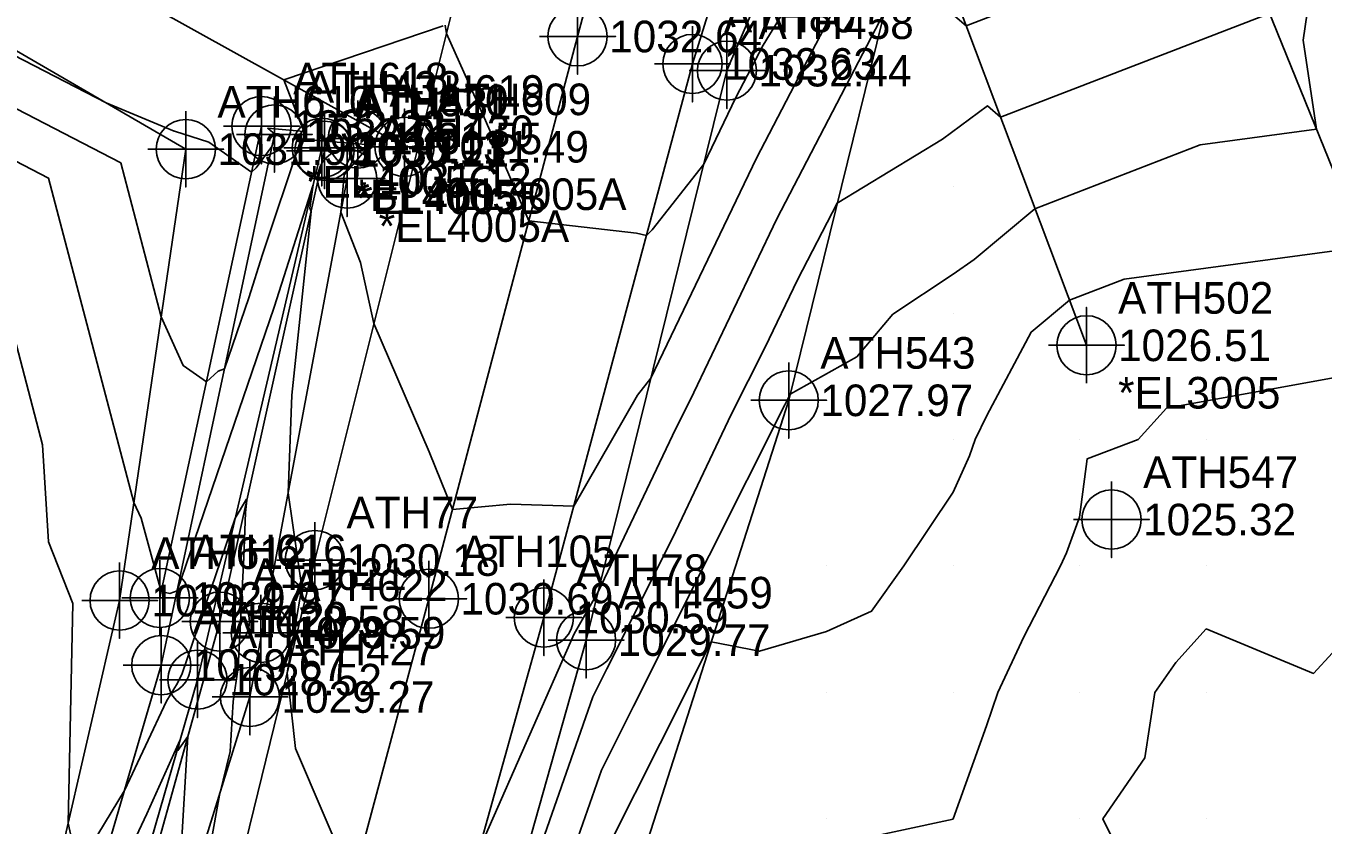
# Model space of a CAD drawing. Extents: x 1213164 to 1213550, y 766120 to 766870.
# Drawn here: x 1213316.7 to 1213419.3, y 766539.5 to 766602.7 of the extents above; entities that cross this region are included whole.
import ezdxf

# ---------------------------------------------------------------- set-up
doc = ezdxf.new("R2010")
doc.units = 0
for name, color, linetype in [('Default', 7, 'Continuous'), ('Exist DTM Breakline', 7, 'Continuous'), ('Exist DTM Breakline Cogo Comment', 7, 'Continuous'), ('Exist DTM Breakline Cogo Elevation', 7, 'Continuous'), ('Exist DTM Breakline Cogo Number', 7, 'Continuous'), ('Exist DTM Breakline Cogo Point CELL', 7, 'Continuous'), ('Exist DTM Crownline', 7, 'Continuous'), ('Exist DTM Crownline Cogo Elevation', 7, 'Continuous'), ('Exist DTM Crownline Cogo Number', 7, 'Continuous'), ('Exist DTM Crownline Cogo Point CELL', 7, 'Continuous'), ('Exist DTM QL2 LIDAR Elevation Point', 7, 'Continuous'), ('Exist DTM Regular Point CELL', 7, 'Continuous'), ('Exist DTM Regular Point Cogo Elevation', 7, 'Continuous'), ('Exist DTM Regular Point Cogo Number', 7, 'Continuous'), ('Exist Roads EOP', 7, 'Continuous'), ('Exist Roads EOP Cogo Elevation', 7, 'Continuous'), ('Exist Roads EOP Cogo Number', 7, 'Continuous'), ('Exist Roads EOP Cogo Point CELL', 7, 'Continuous'), ('Exist Roads Soil', 7, 'Continuous'), ('Exist Roads Soil Cogo Comment', 7, 'Continuous'), ('Exist Roads Soil Cogo Elevation', 7, 'Continuous'), ('Exist Roads Soil Cogo Number', 7, 'Continuous'), ('Exist Roads Soil Cogo Point CELL', 7, 'Continuous')]:
    doc.layers.add(name, color=color, linetype=linetype)

msp = doc.modelspace()

# ---------------------------------------------------------------- linework, layer by layer
at = {"layer": 'Default'}
for points in [[(1213353.03, 766538.71), (1213360.06, 766554.63), (1213361.94, 766557.96), (1213368.09, 766570.88), (1213369.21, 766573.11), (1213376.08, 766587.44), (1213384.56, 766603.77), (1213386.66, 766605.05), (1213387.56, 766605.71), (1213391.04, 766602.72), (1213405.84, 766608.43), (1213411.21, 766613.12), (1213411.8, 766620.77), (1213412.59, 766627.41), (1213412.01, 766629.52), (1213413.41, 766632.98), (1213419.7, 766639.25), (1213420, 766639.17), (1213420.37, 766639.63), (1213420.63, 766640), (1213424.33, 766645.67), (1213426.37, 766650), (1213427.85, 766652.15), (1213430, 766656.29)], [(1213353.14, 766525.66), (1213361.52, 766549.65), (1213362.63, 766551.86), (1213367.85, 766562.26), (1213372.47, 766571.97), (1213375.15, 766577.31), (1213377.7, 766582.63), (1213380.85, 766588.68), (1213389.17, 766593.76), (1213392.72, 766596.38), (1213393.76, 766595.49), (1213414.67, 766603.56), (1213414.97, 766603.82), (1213415.01, 766604.26), (1213417.21, 766622.79), (1213415.71, 766628.28), (1213420, 766627.19)], [(1213356.49, 766527.5), (1213362.2, 766543.86), (1213364.74, 766548.91), (1213376.71, 766572.75), (1213376.86, 766573.06), (1213377.13, 766573.6), (1213382.4, 766576.55), (1213385.24, 766579.91), (1213390, 766583.08), (1213391.68, 766584.23), (1213396.48, 766588.25), (1213409.54, 766593.3), (1213418.74, 766594.53), (1213417.67, 766601.59), (1213418.64, 766608.1), (1213420, 766614.82)], [(1213304.7, 766601.97), (1213324.2, 766591.88), (1213327.4, 766579.7), (1213329.15, 766575.85), (1213330.98, 766574.56), (1213331.9, 766575.41), (1213332.4, 766575.6), (1213334.32, 766581.21), (1213335.41, 766584.62), (1213338.39, 766593.55), (1213338.09, 766593.79), (1213343.9, 766593.31), (1213343.81, 766593.21), (1213341.87, 766590.92), (1213341.6, 766587.97), (1213343.17, 766584), (1213344.22, 766579.18), (1213348.58, 766569.03), (1213350.43, 766564.48), (1213355.02, 766564.88), (1213360.02, 766564.74), (1213365.05, 766573.5), (1213366.12, 766574.86), (1213374.46, 766592.25), (1213381.5, 766605.8)], [(1213305.99, 766605.45), (1213323.05, 766596.62), (1213328.43, 766594.38), (1213328.45, 766594.38), (1213331.18, 766593.52), (1213334.55, 766591.15), (1213334.92, 766591.49), (1213336.14, 766593.18), (1213336.45, 766594.1), (1213335.83, 766594.61), (1213338.68, 766594.37), (1213337.1, 766598.45), (1213349.69, 766602.72)], [(1213349.86, 766602.78), (1213349.95, 766602.12), (1213353.05, 766595.24), (1213356.46, 766587.3), (1213364.99, 766586.31), (1213365.76, 766586.13), (1213366.22, 766586.57), (1213370.3, 766591.77), (1213372.84, 766597.06), (1213374.99, 766601.19), (1213376.71, 766603.99)], [(1213303.41, 766598.49), (1213318.49, 766590.68), (1213325.25, 766565.01), (1213325.81, 766563.78), (1213327.41, 766557.97), (1213328.09, 766557.82), (1213328.66, 766558.03), (1213336.34, 766580.47), (1213339.42, 766590.13), (1213339.16, 766588.3), (1213339.25, 766588.02), (1213337.74, 766573.52), (1213337.45, 766565.79), (1213338.52, 766558.29), (1213337.37, 766551.56), (1213338.03, 766545.56), (1213342.55, 766534.96)], [(1213312.79, 766589.49), (1213318.03, 766569.59), (1213318.49, 766561.9), (1213320.42, 766557.04), (1213320.05, 766539.66), (1213320.82, 766536.16), (1213324.49, 766542.24), (1213327.82, 766549.3), (1213328.69, 766550.73), (1213329.06, 766551.49), (1213333.25, 766563.77), (1213334.15, 766565.28), (1213334.18, 766565.2), (1213334.08, 766564.24), (1213333.94, 766560.68), (1213333.49, 766551.98), (1213333.09, 766549.29), (1213332.85, 766545.34), (1213332.01, 766541.89), (1213329.93, 766530.39)], [(1213362.88, 766538.06), (1213366.85, 766545.97), (1213370.89, 766554.01), (1213374.7, 766553.26), (1213380, 766554.82), (1213383.56, 766556.44), (1213386.12, 766560), (1213390, 766565.83), (1213391.29, 766568.71), (1213391.76, 766570), (1213392.68, 766571.89), (1213396.19, 766578.5), (1213399.2, 766581.02), (1213403.52, 766582.69), (1213422.5, 766585.23)], [(1213381.8, 766538.2), (1213390, 766539.99), (1213390, 766539.99), (1213390.01, 766540), (1213392.64, 766547.36), (1213393.53, 766550), (1213395.59, 766554.41), (1213398.5, 766560), (1213398.97, 766561.03), (1213400, 766563.85), (1213400.61, 766568.48), (1213404.63, 766570), (1213406.87, 766572.47), (1213424.68, 766575.72)], [(1213403.65, 766536.35), (1213401.85, 766540), (1213405.16, 766544.84), (1213405.95, 766550), (1213407.62, 766552.38), (1213410, 766555.03), (1213418.49, 766551.51), (1213420, 766553.14), (1213421.59, 766550), (1213421.87, 766548.13), (1213424.23, 766540), (1213426.51, 766533.49)], [(1213320.12, 766527.35), (1213326.28, 766540.39), (1213328.88, 766546.21), (1213328.73, 766545.41), (1213329.52, 766546.52), (1213328.95, 766537.12)]]:
    msp.add_lwpolyline(points, dxfattribs=at)
at = {"layer": 'Exist DTM Breakline'}
msp.add_line((1213335.33, 766594.79), (1213327.3, 766557.47), dxfattribs=at)
for points in [[(1213396.81, 766643.38), (1213385.25, 766629.79), (1213372.13, 766599.17), (1213360.99, 766554.14), (1213352.93, 766525.55), (1213348.45, 766509.5)], [(1213233.32, 766620.63), (1213306.32, 766606.35), (1213329.35, 766592.96), (1213324.12, 766557.27), (1213317.07, 766526.75)], [(1213385.82, 766608.86), (1213377.01, 766573.1), (1213363.67, 766531.44)], [(1213318.46, 766521.69), (1213327.41, 766552.16), (1213336.35, 766594.13)], [(1213340.32, 766592.83), (1213332.04, 766555.6), (1213323.54, 766524.98), (1213320.37, 766516.25)], [(1213321.01, 766518.9), (1213330.27, 766551.01), (1213340.1, 766593.06)], [(1213324.6, 766518.12), (1213334.42, 766549.64), (1213342.1, 766590.63)]]:
    msp.add_lwpolyline(points, dxfattribs=at)
at = {"layer": 'Exist DTM Breakline Cogo Point CELL'}
for points in [[(1213372.13, 766602.17), (1213372.13, 766596.17), (1213372.13, 766599.17), (1213375.13, 766599.17), (1213369.13, 766599.17)], [(1213335.33, 766597.79), (1213335.33, 766591.79), (1213335.33, 766594.79), (1213338.33, 766594.79), (1213332.33, 766594.79)], [(1213336.35, 766597.13), (1213336.35, 766591.13), (1213336.35, 766594.13), (1213339.35, 766594.13), (1213333.35, 766594.13)], [(1213329.35, 766595.96), (1213329.35, 766589.96), (1213329.35, 766592.96), (1213332.35, 766592.96), (1213326.35, 766592.96)], [(1213340.1, 766596.06), (1213340.1, 766590.06), (1213340.1, 766593.06), (1213343.1, 766593.06), (1213337.1, 766593.06)], [(1213342.94, 766596.81), (1213342.94, 766590.81), (1213342.94, 766593.81), (1213345.94, 766593.81), (1213339.94, 766593.81)], [(1213340.32, 766595.83), (1213340.32, 766589.83), (1213340.32, 766592.83), (1213343.32, 766592.83), (1213337.32, 766592.83)], [(1213342.1, 766593.63), (1213342.1, 766587.63), (1213342.1, 766590.63), (1213345.1, 766590.63), (1213339.1, 766590.63)], [(1213377.01, 766576.1), (1213377.01, 766570.1), (1213377.01, 766573.1), (1213380.01, 766573.1), (1213374.01, 766573.1)], [(1213324.12, 766560.27), (1213324.12, 766554.27), (1213324.12, 766557.27), (1213327.12, 766557.27), (1213321.12, 766557.27)], [(1213327.3, 766560.47), (1213327.3, 766554.47), (1213327.3, 766557.47), (1213330.3, 766557.47), (1213324.3, 766557.47)], [(1213332.04, 766558.6), (1213332.04, 766552.6), (1213332.04, 766555.6), (1213335.04, 766555.6), (1213329.04, 766555.6)], [(1213335.28, 766557.72), (1213335.28, 766551.72), (1213335.28, 766554.72), (1213338.28, 766554.72), (1213332.28, 766554.72)], [(1213360.99, 766557.14), (1213360.99, 766551.14), (1213360.99, 766554.14), (1213363.99, 766554.14), (1213357.99, 766554.14)], [(1213327.41, 766555.16), (1213327.41, 766549.16), (1213327.41, 766552.16), (1213330.41, 766552.16), (1213324.41, 766552.16)], [(1213330.27, 766554.01), (1213330.27, 766548.01), (1213330.27, 766551.01), (1213333.27, 766551.01), (1213327.27, 766551.01)], [(1213334.42, 766552.64), (1213334.42, 766546.64), (1213334.42, 766549.64), (1213337.42, 766549.64), (1213331.42, 766549.64)]]:
    msp.add_lwpolyline(points, dxfattribs=at)
for centre in [(1213372.13, 766599.17), (1213335.33, 766594.79), (1213336.35, 766594.13), (1213342.94, 766593.81), (1213329.35, 766592.96), (1213340.1, 766593.06), (1213340.32, 766592.83), (1213342.1, 766590.63), (1213377.01, 766573.1), (1213324.12, 766557.27), (1213327.3, 766557.47), (1213332.04, 766555.6), (1213335.28, 766554.72), (1213360.99, 766554.14), (1213327.41, 766552.16), (1213330.27, 766551.01), (1213334.42, 766549.64)]:
    msp.add_circle(centre, 2.34, dxfattribs=at)
at = {"layer": 'Exist DTM Crownline'}
msp.add_lwpolyline([(1213369.87, 766637.44), (1213360.32, 766601.88), (1213348.56, 766557.41), (1213336.15, 766511.05)], dxfattribs=at)
at = {"layer": 'Exist DTM Crownline Cogo Point CELL'}
for points in [[(1213360.32, 766604.88), (1213360.32, 766598.88), (1213360.32, 766601.88), (1213363.32, 766601.88), (1213357.32, 766601.88)], [(1213348.56, 766560.41), (1213348.56, 766554.41), (1213348.56, 766557.41), (1213351.56, 766557.41), (1213345.56, 766557.41)]]:
    msp.add_lwpolyline(points, dxfattribs=at)
for centre in [(1213360.32, 766601.88), (1213348.56, 766557.41)]:
    msp.add_circle(centre, 2.34, dxfattribs=at)
at = {"layer": 'Exist DTM QL2 LIDAR Elevation Point'}
for p, q in [((1213390, 766590), (1213390, 766590)), ((1213390, 766580), (1213390, 766580)), ((1213390, 766570), (1213390, 766570)), ((1213400, 766570), (1213400, 766570)), ((1213410, 766570), (1213410, 766570)), ((1213380, 766560), (1213380, 766560)), ((1213390, 766560), (1213390, 766560)), ((1213400, 766560), (1213400, 766560)), ((1213410, 766560), (1213410, 766560)), ((1213380, 766550), (1213380, 766550)), ((1213390, 766550), (1213390, 766550)), ((1213400, 766550), (1213400, 766550)), ((1213410, 766550), (1213410, 766550)), ((1213380, 766540), (1213380, 766540)), ((1213390, 766540), (1213390, 766540)), ((1213400, 766540), (1213400, 766540)), ((1213410, 766540), (1213410, 766540))]:
    msp.add_line(p, q, dxfattribs=at)
at = {"layer": 'Exist DTM Regular Point CELL'}
msp.add_lwpolyline([(1213402.53, 766566.67), (1213402.53, 766560.67), (1213402.53, 766563.67), (1213405.53, 766563.67), (1213399.53, 766563.67)], dxfattribs=at)
msp.add_circle((1213402.53, 766563.67), 2.34, dxfattribs=at)
at = {"layer": 'Exist Roads EOP'}
for points in [[(1213344.56, 766509.06), (1213357.66, 766555.92), (1213369.4, 766599.7), (1213380.5, 766635.51), (1213390.23, 766668.75)], [(1213327.95, 766513.13), (1213339.55, 766560.47), (1213350.85, 766605.72), (1213360.68, 766641.43)]]:
    msp.add_lwpolyline(points, dxfattribs=at)
at = {"layer": 'Exist Roads EOP Cogo Point CELL'}
for points in [[(1213369.4, 766602.7), (1213369.4, 766596.7), (1213369.4, 766599.7), (1213372.4, 766599.7), (1213366.4, 766599.7)], [(1213339.55, 766563.47), (1213339.55, 766557.47), (1213339.55, 766560.47), (1213342.55, 766560.47), (1213336.55, 766560.47)], [(1213357.66, 766558.92), (1213357.66, 766552.92), (1213357.66, 766555.92), (1213360.66, 766555.92), (1213354.66, 766555.92)]]:
    msp.add_lwpolyline(points, dxfattribs=at)
for centre in [(1213369.4, 766599.7), (1213339.55, 766560.47), (1213357.66, 766555.92)]:
    msp.add_circle(centre, 2.34, dxfattribs=at)
at = {"layer": 'Exist Roads Soil'}
msp.add_line((1213426.4, 766575.59), (1213398.12, 766645.45), dxfattribs=at)
for points in [[(1213233.88, 766629.04), (1213261.45, 766622.83), (1213319.9, 766608), (1213346.63, 766593.15)], [(1213384.45, 766620.24), (1213400.55, 766577.45)]]:
    msp.add_lwpolyline(points, dxfattribs=at)
at = {"layer": 'Exist Roads Soil Cogo Point CELL'}
for points in [[(1213346.63, 766590.15), (1213346.63, 766596.15), (1213346.63, 766593.15), (1213349.63, 766593.15), (1213343.63, 766593.15)], [(1213400.55, 766574.45), (1213400.55, 766580.45), (1213400.55, 766577.45), (1213403.55, 766577.45), (1213397.55, 766577.45)]]:
    msp.add_lwpolyline(points, dxfattribs=at)
for centre in [(1213346.63, 766593.15), (1213400.55, 766577.45)]:
    msp.add_circle(centre, 2.34, dxfattribs=at)

# ---------------------------------------------------------------- texts
at = {"layer": 'Exist DTM Breakline Cogo Comment'}
for s, p in [('*EL4005C', (1213338.85, 766589.13)), ('*BL4005', (1213342.6, 766588.06)), ('*EL4005B', (1213342.82, 766587.83)), ('*EL4005A', (1213344.6, 766585.63))]:
    msp.add_text(s, height=2.5, dxfattribs=at).set_placement(p)
at = {"layer": 'Exist DTM Breakline Cogo Elevation'}
for s, p in [('1032.44', (1213374.63, 766597.92)), ('1032.22', (1213337.83, 766593.54)), ('1032.05', (1213338.85, 766592.88)), ('1031.55', (1213345.44, 766592.56)), ('1031.90', (1213331.85, 766591.71)), ('1030.11', (1213342.6, 766591.81)), ('1030.21', (1213342.82, 766591.58)), ('1031.12', (1213344.6, 766589.38)), ('1027.97', (1213379.51, 766571.85)), ('1029.47', (1213326.62, 766556.02)), ('1029.97', (1213329.8, 766556.22)), ('1028.58', (1213334.54, 766554.35)), ('1029.59', (1213337.78, 766553.47)), ('1029.77', (1213363.49, 766552.89)), ('1029.67', (1213329.91, 766550.91)), ('1028.52', (1213332.77, 766549.76)), ('1029.27', (1213336.92, 766548.39))]:
    msp.add_text(s, height=2.5, dxfattribs=at).set_placement(p)
at = {"layer": 'Exist DTM Breakline Cogo Number'}
for s, p in [('ATH458', (1213374.63, 766601.67)), ('ATH618', (1213337.83, 766597.29)), ('ATH432', (1213338.85, 766596.63)), ('ATH610', (1213331.85, 766595.46)), ('ATH620', (1213342.6, 766595.56)), ('ATH619', (1213345.44, 766596.31)), ('ATH431', (1213342.82, 766595.33)), ('ATH430', (1213344.6, 766593.13)), ('ATH543', (1213379.51, 766575.6)), ('ATH612', (1213326.62, 766559.77)), ('ATH616', (1213329.8, 766559.97)), ('ATH621', (1213334.54, 766558.1)), ('ATH622', (1213337.78, 766557.22)), ('ATH459', (1213363.49, 766556.64)), ('ATH429', (1213329.91, 766554.66)), ('ATH428', (1213332.77, 766553.51)), ('ATH427', (1213336.92, 766552.14))]:
    msp.add_text(s, height=2.5, dxfattribs=at).set_placement(p)
at = {"layer": 'Exist DTM Crownline Cogo Elevation'}
for s, p in [('1032.64', (1213362.82, 766600.62)), ('1030.69', (1213351.06, 766556.16))]:
    msp.add_text(s, height=2.5, dxfattribs=at).set_placement(p)
at = {"layer": 'Exist DTM Crownline Cogo Number'}
msp.add_text('ATH105', height=2.5, dxfattribs=at).set_placement((1213351.06, 766559.91))
at = {"layer": 'Exist DTM Regular Point Cogo Elevation'}
msp.add_text('1025.32', height=2.5, dxfattribs=at).set_placement((1213405.03, 766562.42))
at = {"layer": 'Exist DTM Regular Point Cogo Number'}
msp.add_text('ATH547', height=2.5, dxfattribs=at).set_placement((1213405.03, 766566.17))
at = {"layer": 'Exist Roads EOP Cogo Elevation'}
for s, p in [('1032.63', (1213371.9, 766598.45)), ('1030.18', (1213342.05, 766559.22)), ('1030.59', (1213360.16, 766554.67))]:
    msp.add_text(s, height=2.5, dxfattribs=at).set_placement(p)
at = {"layer": 'Exist Roads EOP Cogo Number'}
for s, p in [('ATH80', (1213371.9, 766602.2)), ('ATH77', (1213342.05, 766562.97)), ('ATH78', (1213360.16, 766558.42))]:
    msp.add_text(s, height=2.5, dxfattribs=at).set_placement(p)
at = {"layer": 'Exist Roads Soil Cogo Comment'}
for s, p in [('*EL3005A', (1213349.13, 766588.15)), ('*EL3005', (1213403.05, 766572.45))]:
    msp.add_text(s, height=2.5, dxfattribs=at).set_placement(p)
at = {"layer": 'Exist Roads Soil Cogo Elevation'}
for s, p in [('1031.49', (1213349.13, 766591.9)), ('1026.51', (1213403.05, 766576.2))]:
    msp.add_text(s, height=2.5, dxfattribs=at).set_placement(p)
at = {"layer": 'Exist Roads Soil Cogo Number'}
for s, p in [('ATH609', (1213349.13, 766595.65)), ('ATH502', (1213403.05, 766579.95))]:
    msp.add_text(s, height=2.5, dxfattribs=at).set_placement(p)

doc.saveas('drawing.dxf')
